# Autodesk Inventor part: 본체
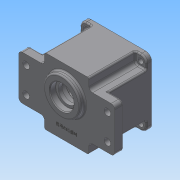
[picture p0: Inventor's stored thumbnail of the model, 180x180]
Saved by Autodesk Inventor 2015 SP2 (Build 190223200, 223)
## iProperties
Created: 2015-06
Part Number: 본체
Material: 일반
Document SubType Name: Modeling
Designer: AMC
Density: 1 g/cm^3
Appearance: 기본값
Author: AMC
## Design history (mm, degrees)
sketch "스케치1"
  geometry: L1 (-65, 30)-(-65, -30); L2 (65, -30)-(65, 30); L3 (30, 45)-(-30, 45); L4 (-30, -45)-(30, -45); L5 (65, 30)-(30, 30); L6 (-30, 30)-(-65, 30); L7 (-30, 45)-(-30, 30); L8 (-30, -30)-(-30, -45); L9 (-65, -30)-(-30, -30); L10 (30, -30)-(65, -30); L11 (30, -45)-(30, -30); L12 (30, 30)-(30, 45); 5 further points
  constraints: 24 end point, 10 parallel, 4 midpoint, 4 perpendicular, 3 horizontal, 2 horizontal alignment, 2 vertical alignment
  dimensions: "d0" = 130 distance between parallel lines of L1 L2; "d1" = 60 distance of L3.start L3.end; "d2" = 60 distance between parallel lines of L10 L5; "d3" = 60 distance of L1.start L1.end; "d4" = 60 distance of L4.start L4.end; "d6" = 45 distance from line of point (0, 0) L3; "d7" = 45 distance from line of point (0, 0) L4; "d8" = 65 distance from line of point (0, 0) L2
extrude "돌출1" new body sketch "스케치1" distance "d9" = 12; taper "d10" = 0 deg
sketch "스케치2"
  geometry: L1 (-55, -17.5)-(-55, 17.5); C1 r 4.5 at (-55, 17.5); C2 r 4.5 at (55, 17.5); C3 r 4.5 at (55, -17.5); C4 r 4.5 at (-55, -17.5); 2 further points
  constraints: 4 centre point, 3 horizontal alignment, 2 end point, 1 midpoint, 1 vertical
  dimensions: "d11" = 9 diameter of C1; "d12" = 9 diameter of C2; "d13" = 9 diameter of C3; "d14" = 9 diameter of C4; "d15" = 35 distance of L1.start L1.end; "d16" = 35 distance of C3.centre C2.centre; "d17" = 110 distance of C2.centre L1.end; "d18" = 55 horizontal distance of L1.end point (0, 0)
extrude "돌출2" cut sketch "스케치2" distance "d19" = 12; taper "d20" = 0 deg
sketch "스케치3"
  geometry: L1 (45, -45)-(-45, -45); L2 (-45, -45)-(-45, 45); L3 (-45, 45)-(45, 45); L4 (45, 45)-(45, -45); 3 further points
  constraints: 8 end point, 2 midpoint, 2 parallel, 2 perpendicular, 1 horizontal, 1 horizontal alignment, 1 vertical alignment
  dimensions: "d22" = 90 distance of L1.start L1.end
extrude "돌출3" join sketch "스케치3" distance "d23" = 58; taper "d24" = 0 deg
sketch "스케치5"
  geometry: C1 r 25 at (0, 11); 1 further point
  constraints: 1 centre point, 1 vertical alignment
  dimensions: "d30" = 50 diameter of C1; "d31" = 11 distance of point (0, 0) C1.centre
extrude "돌출4" join sketch "스케치5" distance "d32" = 7; taper "d33" = 0 deg
sketch "스케치6"
  geometry: L1 (30, 30)-(45, 30) reference; L2 (45, 30)-(45, 45) reference; L3 (45, 45)-(30, 45) reference; L4 (30, 45)-(30, 30) reference; L5 (-45, 30)-(-30, 30) reference; L6 (-30, 30)-(-30, 45) reference; L7 (-30, 45)-(-45, 45) reference; L8 (-45, 45)-(-45, 30) reference; L9 (-30, -45)-(-30, -30) reference; L10 (-30, -30)-(-45, -30) reference; L11 (-45, -30)-(-45, -45) reference; L12 (-45, -45)-(-30, -45) reference; L13 (45, -45)-(45, -30) reference; L14 (30, -30)-(30, -45) reference; L15 (30, -45)-(45, -45) reference; L16 (45, -45)-(45, -30) reference; L17 (45, -30)-(30, -30) reference; L18 (-45, 45)-(-30, 45); L19 (-30, 45)-(-30, 30); L20 (-30, 30)-(-45, 30); L21 (-45, 30)-(-45, 45); L22 (30, 45)-(45, 45); L23 (45, 45)-(45, 30); L24 (45, 30)-(30, 30); L25 (30, 30)-(30, 45); L26 (45, -45)-(30, -45); L27 (30, -45)-(30, -30); L28 (30, -30)-(45, -30); L29 (45, -30)-(45, -45); L30 (-45, -45)-(-30, -45); L31 (-30, -45)-(-30, -30); L32 (-30, -30)-(-45, -30); L33 (-45, -30)-(-45, -45); 1 further point
  constraints: 32 end point, 8 parallel, 4 horizontal, 4 perpendicular
extrude "돌출5" cut sketch "스케치6" distance "d34" = 51; taper "d35" = 0 deg
fillet "모깎기3" dims "d36" = 5
fillet "모깎기4" dims "d37" = 2
fillet "모깎기5" dims "d38" = 8
sketch "스케치7"
  geometry: C1 r 3.5 at (37, -37); C2 r 3.5 at (-37, -37); C3 r 3.5 at (-37, 37); C4 r 3.5 at (37, 37); A1 r 8 centre (37, -37) between (37, -45) and (45, -37) reference; A2 r 8 centre (-37, -37) between (-45, -37) and (-37, -45) reference; A3 r 8 centre (-37, 37) between (-37, 45) and (-45, 37) reference; A4 r 8 centre (37, 37) between (45, 37) and (37, 45) reference; 1 further point
  constraints: 4 centre point, 4 coincident
  dimensions: "d39" = 7 diameter of C1; "d40" = 7 diameter of C2; "d41" = 7 diameter of C3; "d42" = 7 diameter of C4
extrude "돌출6" cut sketch "스케치7" distance "d43" = 51; taper "d44" = 0 deg
fillet "모깎기6" dims "d45" = 2
sketch "스케치8"
  geometry: C1 r 39 at (0, 0); 1 further point
  constraints: 1 centre point, 1 coincident
  dimensions: "d46" = 78 diameter of C1
extrude "돌출7" cut sketch "스케치8" distance "d47" = 9; taper "d48" = 0 deg
sketch "스케치9"
  geometry: L1 (0, 0)-(-24.749, -24.749); L2 (0, 0)-(-35, 0); A1 r 35 centre (0, 0) between (-24.749, -24.749) and (-35, 0); A2 r 4 centre (-24.749, -24.749) between (-21.809, -27.462) and (-27.462, -21.809); A3 r 39 centre (0, 0) between (-21.134, -32.777) and (-32.777, -21.134) reference; A4 r 3.5 centre (-19.238, -29.836) between (-21.762, -27.412) and (-21.134, -32.777); A5 r 3.5 centre (-29.836, -19.238) between (-32.777, -21.134) and (-27.412, -21.762); A6 r 4 centre (24.749, -24.749) between (27.462, -21.809) and (21.809, -27.462); A7 r 3.5 centre (29.836, -19.238) between (27.412, -21.762) and (32.777, -21.134); A8 r 3.5 centre (19.238, -29.836) between (21.134, -32.777) and (21.762, -27.412); A9 r 4 centre (24.749, 24.749) between (21.809, 27.462) and (27.462, 21.809); A10 r 3.5 centre (19.238, 29.836) between (21.762, 27.412) and (21.134, 32.777); A11 r 3.5 centre (29.836, 19.238) between (32.777, 21.134) and (27.412, 21.762); A12 r 4 centre (-24.749, 24.749) between (-27.462, 21.809) and (-21.809, 27.462); A13 r 3.5 centre (-29.836, 19.238) between (-27.412, 21.762) and (-32.777, 21.134); A14 r 3.5 centre (-19.238, 29.836) between (-21.134, 32.777) and (-21.762, 27.412); A15 r 39 centre (0, 0) between (21.134, -32.777) and (32.777, -21.134); A16 r 39 centre (0, 0) between (32.777, 21.134) and (21.134, 32.777); A17 r 39 centre (0, 0) between (-21.134, 32.777) and (-32.777, 21.134); A18 r 39 centre (0, 0) between (-32.777, -21.134) and (-21.134, -32.777); 1 further point
  constraints: 46 point on circle, 17 centre point, 4 end point, 4 tangent, 3 coincident, 1 horizontal, 49 other
  dimensions: "d49" = 70 diameter of A1; "d50" = 45 deg angle of L1 L2; "d51" = 8 diameter of A2; "d52" = 7 diameter of A4; "d53" = 7 diameter of A5; "d56" = 360 deg dimension on A3.centre A2.centre (derived)
extrude "돌출8" cut sketch "스케치9" distance "d58" = 45; taper "d59" = 0 deg
sketch "스케치11"
  geometry: C1 r 17.5 at (0, -11); 1 further point
  constraints: 1 centre point, 1 vertical alignment
  dimensions: "d67" = 35 diameter of C1; "d68" = 11 distance of point (0, 0) C1.centre
extrude "돌출9" cut sketch "스케치11" distance "d69" = 10; taper "d70" = 0 deg
sketch "스케치12"
  geometry: L1 (-7, 36)-(-7, -14) reference; L2 (6, 28.5)-(6, -6.5) reference; L3 (-2, 36)-(-7, 36) reference; L4 (0, 45)-(61, 45) reference; L5 (-2, -14)-(-7, -14) reference; L6 (6, 11)-(-7, 11); L7 (-7, 27)-(1, 27); L8 (-2, -14)-(-2, 36) reference; L9 (1, 27)-(1, 23.5); L10 (1, 23.5)-(6, 23.5); 1 further point
  constraints: 8 end point, 3 perpendicular, 2 midpoint, 2 point on line
  dimensions: "d71" = 25 diameter of L10 L6; "d72" = 5 distance of L9.end L10.end; "d73" = 32 diameter of L7 L6
revolve "회전1" sketch "스케치12" stored, may be unused: angle "d74" = 90 deg
sketch "스케치13"
  geometry: L1 (16, 21.134)-(16, -21.134) reference; L2 (16, -27.462)-(16, -20.749) reference; L3 (16, -27.462)-(16, -32.777) reference; L4 (16, -32.777)-(16, -39) reference; L5 (0, -30)-(0, -25) reference; L6 (0, 25)-(0, -25) reference; L7 (0, -35)-(0, -43) reference; L8 (0, -30)-(0, -35) reference; L9 (16, -9)-(9.3, -9); L10 (9, -9.3)-(9, -10.5); L11 (9, -10.5)-(9, -10.5); L12 (8, -11.5)-(8, -20); L13 (8, -20)-(16, -20); L14 (16, -9)-(16, -20); A1 r 0.3 centre (9.3, -9.3) between (9.3, -9) and (9, -9.3); A2 r 1 centre (9, -11.5) between (9, -10.5) and (8, -11.5); 4 further points
  constraints: 12 end point, 6 point on line, 5 perpendicular, 4 point on circle, 4 tangent, 2 centre point, 1 horizontal
  dimensions: "d75" = 20 vertical distance of point (0, 0) L12.end; "d76" = 19 diameter of L11 L13; "d77" = 22 diameter of L9 L13; "d78" = 7 distance of L9.start point (9, -9); "d79" = 1 distance of L10.end point (8, -10.5); "d80" = 0.3 radius of A1; "d81" = 1 radius of A2
revolve "회전2" sketch "스케치13" stored, may be unused: angle "d82" = 90 deg
chamfer "모따기1" distance "d83" = 1; stored, may be unused: second distance "d84" = 2, angle "d85" = 45 deg
sketch "스케치15"
  geometry: C1 r 40 at (0, 0); 1 further point
  constraints: 1 centre point, 1 coincident
  dimensions: "d90" = 80 diameter of C1
extrude "돌출11" cut sketch "스케치15" distance "d91" = 9; taper "d92" = 0 deg
sketch "스케치16"
  geometry: C1 r 40 at (0, 0) reference; A1 r 3.5 centre (19.238, 29.836) between (21.809, 27.462) and (21.134, 32.777) reference; A2 r 4 centre (24.749, 24.749) between (21.809, 27.462) and (27.462, 21.809) reference; A3 r 3.5 centre (29.836, 19.238) between (32.777, 21.134) and (27.462, 21.809) reference; A4 r 39 centre (0, 0) between (32.777, -21.134) and (32.777, 21.134) reference; A5 r 3.5 centre (29.836, -19.238) between (27.462, -21.809) and (32.777, -21.134) reference; A6 r 4 centre (24.749, -24.749) between (27.462, -21.809) and (21.809, -27.462) reference; A7 r 3.5 centre (19.238, -29.836) between (21.134, -32.777) and (21.809, -27.462) reference; A8 r 39 centre (0, 0) between (-21.134, -32.777) and (21.134, -32.777) reference; A9 r 3.5 centre (-19.238, -29.836) between (-21.809, -27.462) and (-21.134, -32.777) reference; A10 r 4 centre (-24.749, -24.749) between (-21.809, -27.462) and (-27.462, -21.809) reference; A11 r 3.5 centre (-29.836, -19.238) between (-32.777, -21.134) and (-27.462, -21.809) reference; A12 r 39 centre (0, 0) between (-32.777, 21.134) and (-32.777, -21.134) reference; A13 r 3.5 centre (-29.836, 19.238) between (-27.462, 21.809) and (-32.777, 21.134) reference; A14 r 4 centre (-24.749, 24.749) between (-27.462, 21.809) and (-21.809, 27.462) reference; A15 r 3.5 centre (-19.238, 29.836) between (-21.134, 32.777) and (-21.809, 27.462) reference; A16 r 39 centre (0, 0) between (21.134, 32.777) and (-21.134, 32.777) reference; 5 further points
  constraints: 4 coincident
hole "구멍2" sketch "스케치16" at (24.749, -24.749), (-24.749, -24.749), (-24.749, 24.749), (24.749, 24.749) diameter "d93" = 3.459; stored, may be unused: countersink angle "d97" = 90 deg, drill point angle "d99" = 118 deg; dims "d94" = 12, "d95" = 4, "d96" = 2, "d98" = 15
sketch "스케치17"
  geometry: C1 r 12.5 at (0, -11) reference; C2 r 8.5 at (0, 20) reference; C3 r 18.5 at (0, -11) reference; C4 r 12 at (0, 20) reference; A1 r 20.5 centre (0, -11) between (-11.115, 6.225) and (11.115, 6.225); A2 r 14 centre (0, 20) between (10.493, 10.732) and (-10.493, 10.732); A3 r 3.5 centre (-29.836, 19.238) between (-27.462, 21.809) and (-32.777, 21.134) reference; A4 r 39 centre (0, 0) between (-32.777, 21.134) and (-32.777, -21.134) reference; A5 r 3.5 centre (-29.836, -19.238) between (-32.777, -21.134) and (-27.462, -21.809) reference; A6 r 4 centre (-24.749, -24.749) between (-21.809, -27.462) and (-27.462, -21.809) reference; A7 r 3.5 centre (-19.238, -29.836) between (-21.809, -27.462) and (-21.134, -32.777) reference; A8 r 39 centre (0, 0) between (-21.134, -32.777) and (21.134, -32.777) reference; A9 r 3.5 centre (19.238, -29.836) between (21.134, -32.777) and (21.809, -27.462) reference; A10 r 4 centre (24.749, -24.749) between (27.462, -21.809) and (21.809, -27.462) reference; A11 r 3.5 centre (29.836, -19.238) between (27.462, -21.809) and (32.777, -21.134) reference; A12 r 39 centre (0, 0) between (32.777, -21.134) and (32.777, 21.134) reference; A13 r 3.5 centre (29.836, 19.238) between (32.777, 21.134) and (27.462, 21.809) reference; A14 r 4 centre (24.749, 24.749) between (21.809, 27.462) and (27.462, 21.809) reference; A15 r 3.5 centre (19.238, 29.836) between (21.809, 27.462) and (21.134, 32.777) reference; A16 r 39 centre (0, 0) between (21.134, 32.777) and (-21.134, 32.777) reference; A17 r 3.5 centre (-19.238, 29.836) between (-21.134, 32.777) and (-21.809, 27.462) reference; A18 r 4 centre (-24.749, 24.749) between (-27.462, 21.809) and (-21.809, 27.462) reference; A19 r 3 centre (12.742, 8.746) between (10.493, 10.732) and (11.115, 6.225); A20 r 3 centre (-12.742, 8.746) between (-11.115, 6.225) and (-10.493, 10.732); 1 further point
  constraints: 8 point on circle, 4 centre point, 4 tangent, 2 coincident
  dimensions: "d100" = 41 diameter of A1; "d101" = 28 diameter of A2; "d110" = 6 diameter of A19; "d111" = 6 diameter of A20
extrude "돌출12" cut sketch "스케치17" distance "d102" = 7; taper "d103" = 0 deg
fillet "모깎기7" dims "d104" = 2
fillet "모깎기8" dims "d105" = 0.3
sketch "스케치18"
  geometry: L1 (-28, -45)-(28, -45) reference; 2 further points
  constraints: 1 vertical alignment, 1 other
  dimensions: "d106" = 15 distance from line of L1 point (0, -30)
feature "엠보싱1" sketch "스케치18" dims "d11" = 9, "d12" = 9, "d13" = 9, "d14" = 9, "d15" = 35, "d16" = 35, "d17" = 110, "d18" = 55, "d107" = 0.5, "d108" = 0
fillet "모깎기9" dims "d109" = 2
fillet "모깎기10" dims "d112" = 2
node "솔리드1"
node "투영된 루프5"
node "투영된 루프6"
node "투영된 루프7"
node "투영된 루프8"
node "투영된 루프16"
node "투영된 루프17"
node "투영된 루프18"
